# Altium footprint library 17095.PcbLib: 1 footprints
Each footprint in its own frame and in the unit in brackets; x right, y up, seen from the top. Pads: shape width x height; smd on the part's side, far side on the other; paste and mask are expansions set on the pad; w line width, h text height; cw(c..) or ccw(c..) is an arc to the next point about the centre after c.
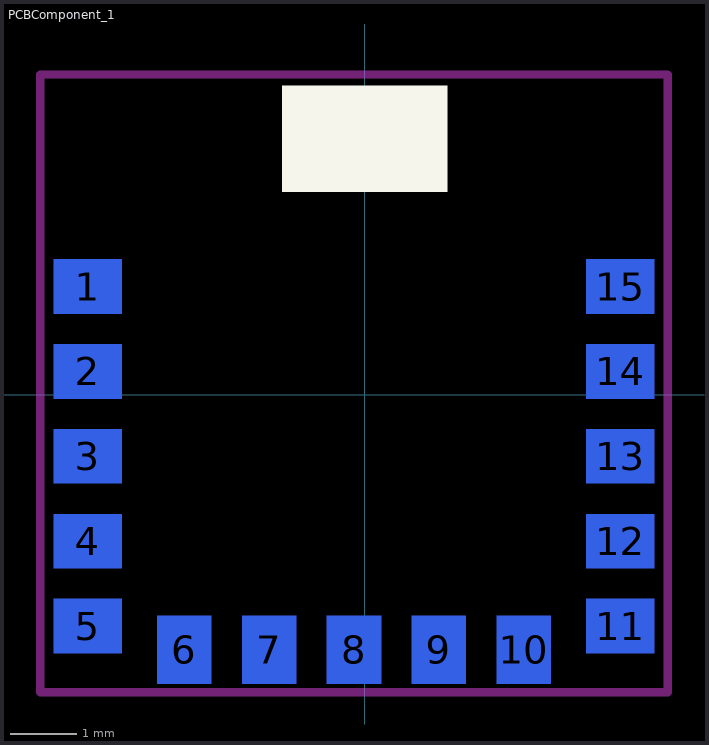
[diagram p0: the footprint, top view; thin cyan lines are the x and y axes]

## PCBComponent_1 [mil]
pads (15):
  rect 40x32 smd far side: 1(-163.34,63.8) 2(-163.34,13.8) 3(-163.34,-36.2) 4(-163.34,-86.2) 5(-163.34,-136.2) 11(150.66,-136.2) 12(150.66,-86.2) 13(150.66,-36.2) 14(150.66,13.8) 15(150.66,63.8)
  rect 32x40 smd far side: 6(-106.34,-150.2) 7(-56.34,-150.2) 8(-6.34,-150.2) 9(43.66,-150.2) 10(93.66,-150.2)
Top Overlay:
  region: 48.89,119.64 48.89,182.28 -48.82,182.28 -48.82,119.64
Bottom Overlay:
  text "HOLYIOT-17095" at 169.29,118.5 h32.68
Keep-Out Layer:
  lines w5: -191.34,-175.2 -191.34,188.8 178.66,188.8 178.66,-175.2 -191.34,-175.2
